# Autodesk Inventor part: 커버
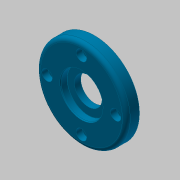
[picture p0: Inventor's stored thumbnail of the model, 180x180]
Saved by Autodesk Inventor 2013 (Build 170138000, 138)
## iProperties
Created: 2016-06
Part Number: 커버
Material: 알루미늄 6061
Document SubType Name: Modeling
Designer: mduedu
Density: 2.71 g/cm^3
Author: mduedu
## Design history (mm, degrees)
sketch "스케치1"
  geometry: C1 r 34 at (0, 0); 1 further point
  constraints: 1 centre point, 1 coincident
  dimensions: "d0" = 68 diameter of C1
extrude "돌출1" new body sketch "스케치1" distance "d2" = 10; taper "d3" = 0 deg
sketch "스케치2"
  geometry: C1 r 21 at (0, 0); 1 further point
  constraints: 1 centre point, 1 coincident
  dimensions: "d4" = 42 diameter of C1
extrude "돌출2" join sketch "스케치2" distance "d6" = 3; taper "d7" = 0 deg
fillet "모깎기1" dims "d8" = 3
hole "구멍1" diameter "d11" = 35; stored, may be unused: countersink angle "d15" = 90 deg, drill point angle "d17" = 0 deg; dims "d9" = 10, "d10" = 10, "d12" = 6, "d13" = 4, "d14" = 2, "d16" = 3
hole "구멍2" diameter "d20" = 32; stored, may be unused: countersink angle "d24" = 90 deg, drill point angle "d26" = 0 deg; dims "d21" = 6, "d22" = 4, "d23" = 2, "d25" = 5.2, "d46" = 10, "d47" = 10
hole "구멍3" diameter "d29" = 21; stored, may be unused: countersink angle "d33" = 90 deg, drill point angle "d35" = 0 deg; dims "d27" = 10, "d28" = 10, "d30" = 6, "d31" = 4, "d32" = 2, "d34" = 5
fillet "모깎기2" dims "d36" = 3
fillet "모깎기3" dims "d37" = 0.1
chamfer "모따기1" distance "d38" = 0.75; stored, may be unused: second distance "d39" = 2, angle "d40" = 30 deg
chamfer "모따기2" distance "d42" = 0.5; stored, may be unused: second distance "d43" = 2, angle "d44" = 30 deg
sketch "스케치3" dims "d48" = 52
  geometry: 6 further points
  constraints: 2 vertical alignment, 1 coincident, 7 other
  dimensions: "d51" = 360 deg dimension on point (0, 0) point (0, 26) (derived)
sketch "스케치4"
  geometry: 4 further points
hole "구멍4" sketch "스케치4" at (0, 26), (-26, 0), (0, -26), (26, 0) diameter "d53" = 4.5; stored, may be unused: countersink angle "d57" = 90 deg, drill point angle "d59" = 0 deg; dims "d54" = 6, "d55" = 8, "d56" = 4.6, "d58" = 8
node "솔리드1"
